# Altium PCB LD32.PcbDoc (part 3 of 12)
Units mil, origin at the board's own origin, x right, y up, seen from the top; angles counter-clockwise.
Board outline 7007.87 x 4368.85 mil, 12 copper layers (Top Layer, Int1 (GND), Int2 (AVDD), Int3 (DVDD), Int4 (GND), Int5 (ST), Int6 (SB), Int8 (AGND), Int7 (AVCC), Int9 (VCCA), Int10 (GND), Bottom Layer), stack 60.136 mil thick; 1165 components, 667 nets, 3910 pads, 2570 vias.
Unrouted connection lines stored in the file: 14.
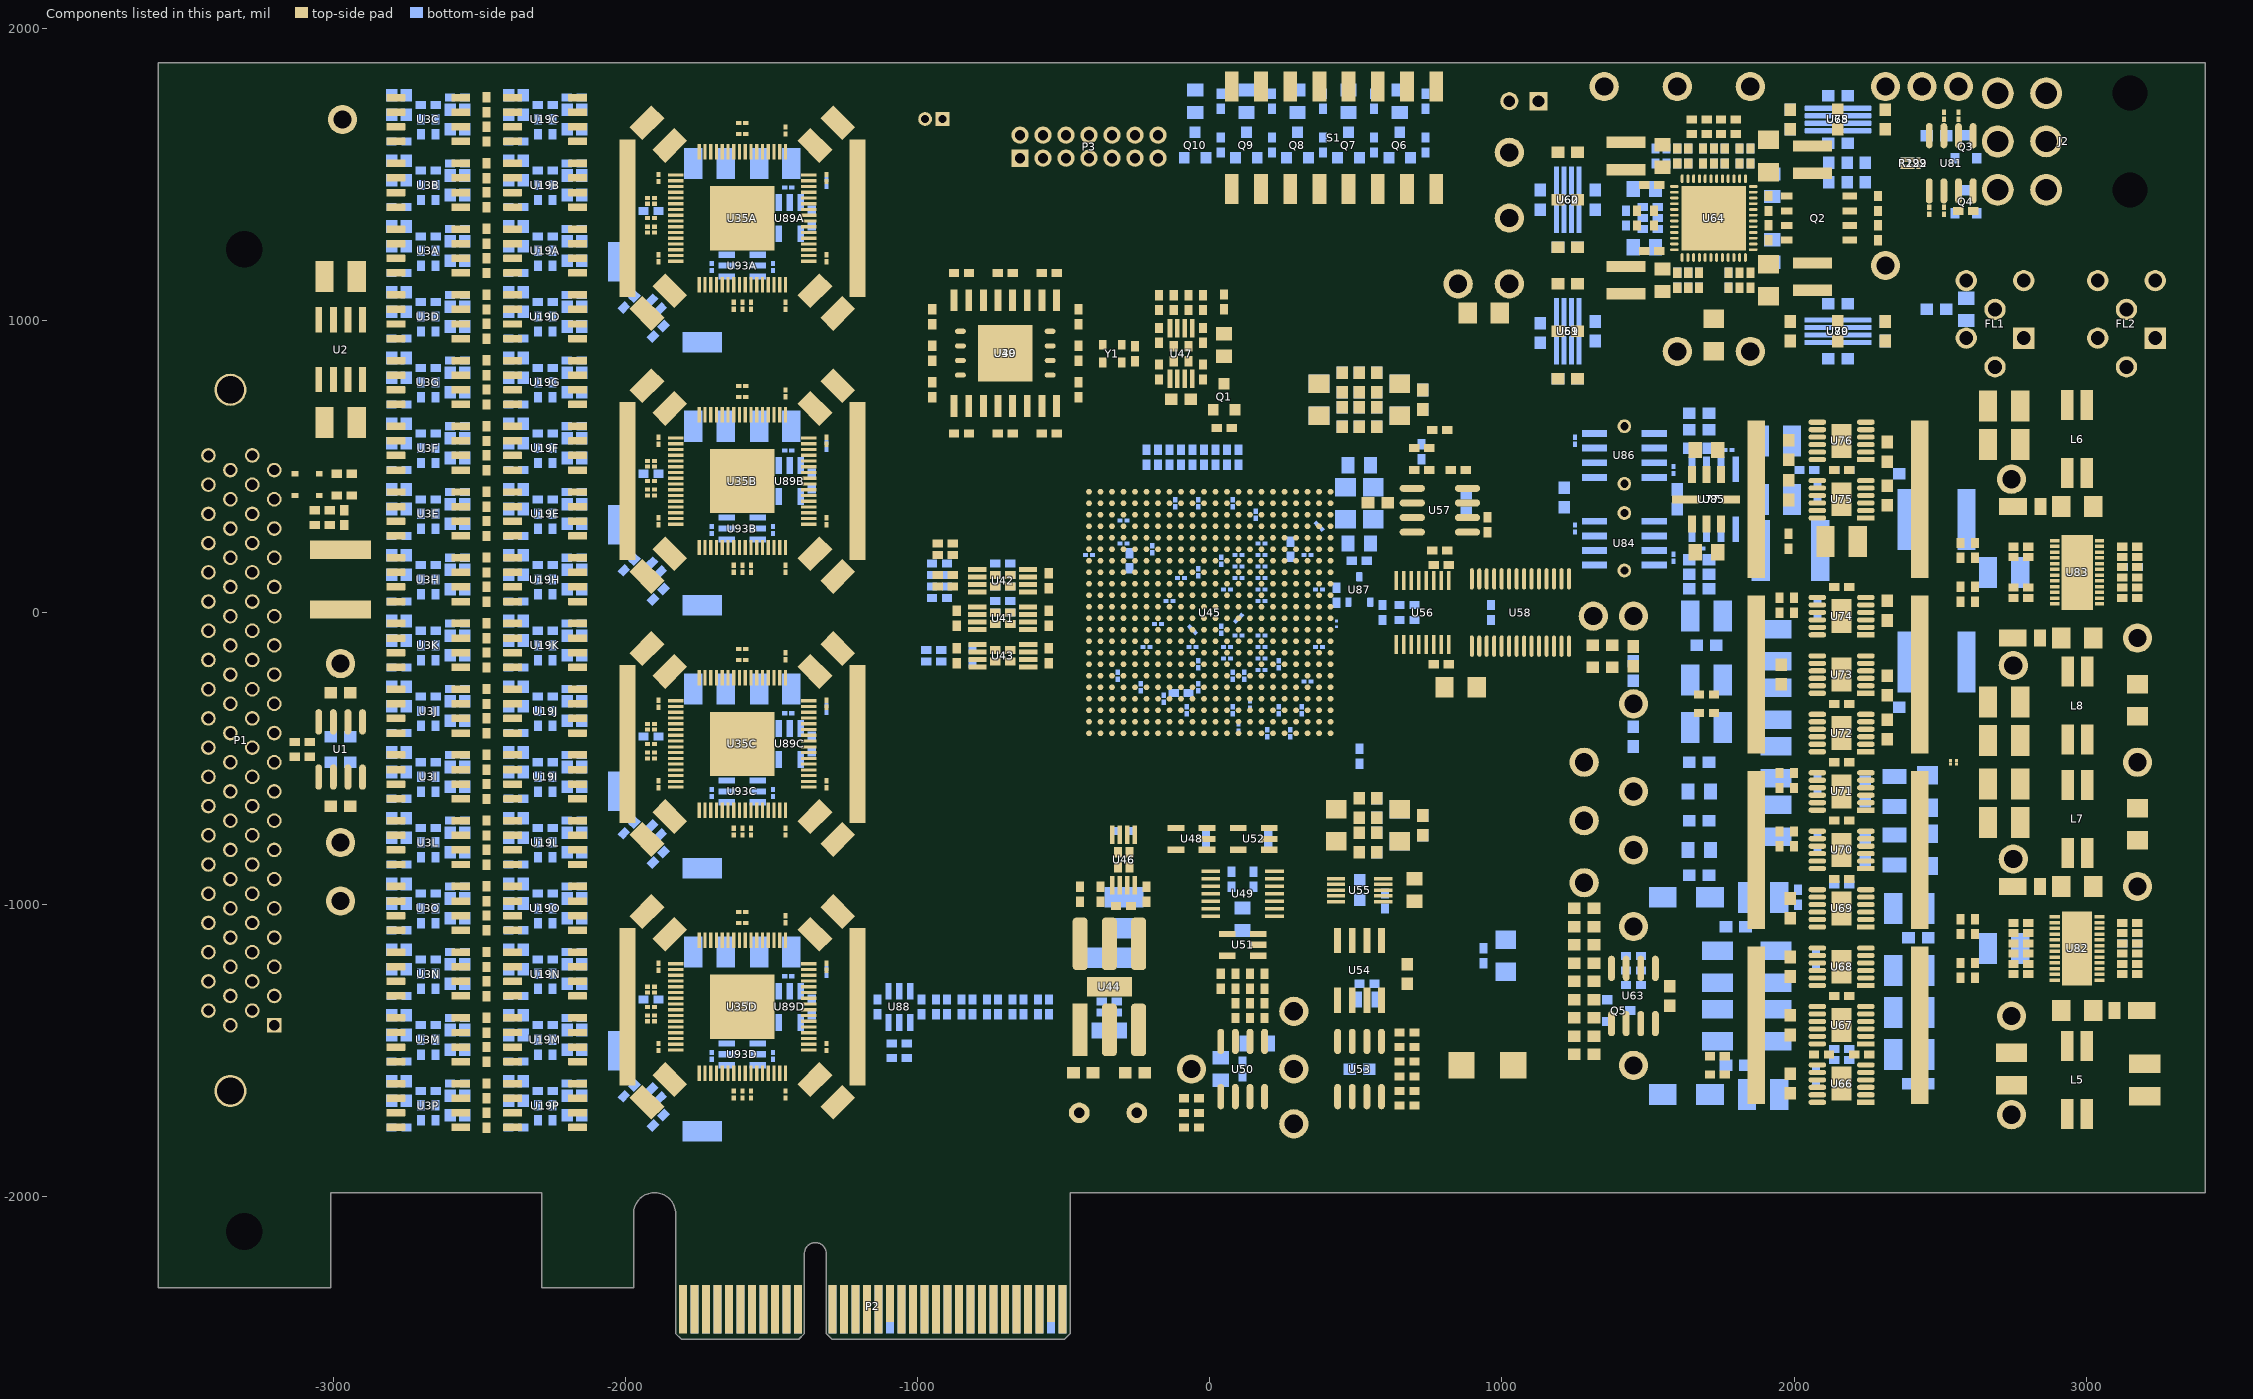
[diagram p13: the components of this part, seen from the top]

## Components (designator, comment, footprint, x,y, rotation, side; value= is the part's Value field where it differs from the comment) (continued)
U19F "OPA1612AID" D0008A_M -2275,562.5 r0 top locked (schematic designator U19)
U19G "OPA1612AID" D0008A_M -2275,787.5 r0 top locked (schematic designator U19)
U19H "OPA1612AID" D0008A_M -2275,112.5 r0 top locked (schematic designator U19)
U19I "OPA1612AID" D0008A_M -2275,-562.5 r0 top locked (schematic designator U19)
U19J "OPA1612AID" D0008A_M -2275,-337.5 r0 top locked (schematic designator U19)
U19K "OPA1612AID" D0008A_M -2275,-112.5 r0 top locked (schematic designator U19)
U19L "OPA1612AID" D0008A_M -2275,-787.5 r0 top locked (schematic designator U19)
U19M "OPA1612AID" D0008A_M -2275,-1462.5 r0 top locked (schematic designator U19)
U19N "OPA1612AID" D0008A_M -2275,-1237.5 r0 top locked (schematic designator U19)
U19O "OPA1612AID" D0008A_M -2275,-1012.5 r0 top locked (schematic designator U19)
U19P "OPA1612AID" D0008A_M -2275,-1687.5 r0 top locked (schematic designator U19)
U35A "ESS9038PRO" CP-64_3_MXM -1600,1350 r270 top locked (schematic designator U35)
U35B "ESS9038PRO" CP-64_3_MXM -1600,450 r270 top locked (schematic designator U35)
U35C "ESS9038PRO" CP-64_3_MXM -1600,-450 r270 top locked (schematic designator U35)
U35D "ESS9038PRO" CP-64_3_MXM -1600,-1350 r270 top locked (schematic designator U35)
U39 "MT25QU512ABB8ESF-0SIT" FP-002-15547-MFG -700,887.5 r90 top
U40 "S25FL256LAGNFV010" FP-002-18827-MFG -700,887.5 r180 top value=NL
U41 "SN65LVDS100D" MSOP8 -708.66,-19.68 r270 top
U42 "SN65LVDS100D" MSOP8 -708.66,108.27 r270 top
U43 "SN65LVDS100D" MSOP8 -708.66,-147.64 r90 top
U44 "67.108864MHz" BomarSiTime -343.75,-1281 r90 top
U45 "XC7A200T-2FBG484I" FBG484 0,0 r180 top locked
U46 "SN65LVDS100D" MSOP8 -295.28,-846.46 r0 top
U47 "SN65LVDS100D" MSOP8 -98.43,885.83 r180 top
U48 "SN65LVDT2" SO-G5/E2.4 -62.5,-775 r90 top
U49 "SN74LVC74APWR" TSSOP14 112.5,-962.5 r90 top
U50 "OP284FS" SO-8_N 112.5,-1562.5 r270 top
U51 "SN74LVC1G00" SO-G5/E2.4 112.5,-1137.5 r90 top
U52 "SN65LVDT2" SO-G5/E2.4 150,-775 r90 top
U53 "OP284FS" SO-8_N 512.5,-1562.5 r90 top
U54 "ADR4530" SO-G8 512.5,-1225 r0 top
U55 "AD7685" TSSO3x5-G10 512.5,-950 r90 top
U56 "SN74LVC4T245" TSSOP16 728.35,0 r180 top locked
U57 "OP284FS" SO-8_N 787.5,350 r180 top
U58 "ADG706BRU" ADI-RU-28_M 1062.99,0 r270 top
U59 "INA333AIDGKR" DGK0008A_N 1225,962.5 r270 bottom
U60 "INA333AIDGKR" DGK0008A_N 1225,1412.5 r270 bottom
U61 "INA350" FP-RJ-8-IPC_B 1225,962.5 r270 bottom value=NL
U62 "INA350" FP-RJ-8-IPC_B 1225,1412.5 r270 bottom value=NL
U63 "OP284FS" SO-8_N 1450,-1312.5 r90 top
U64 "ADP5052ACPZ-R7" CP-48-13_L 1725,1350 r0 top
U65 "INA333AIDGKR" DGK0008A_N 2150,1687.5 r180 bottom
U66 "LT3094IMSE#PBF" FP-MSE-12-05-08-1666-IPC_B 2162.5,-1612.5 r180 top locked
U67 "LT3094IMSE#PBF" FP-MSE-12-05-08-1666-IPC_B 2162.5,-1412.5 r180 top locked
U68 "LT3045EMSE#TRPBF" FP-MSE-12-05-08-1666-IPC_B 2162.5,-1212.5 r180 top locked
U69 "LT3045EMSE#TRPBF" FP-MSE-12-05-08-1666-IPC_B 2162.5,-1012.5 r180 top locked
U70 "LT3045EMSE#TRPBF" FP-MSE-12-05-08-1666-IPC_B 2162.5,-812.5 r180 top locked
U71 "LT3045EMSE#TRPBF" FP-MSE-12-05-08-1666-IPC_B 2162.5,-612.5 r180 top locked
U72 "LT3045EMSE#TRPBF" FP-MSE-12-05-08-1666-IPC_B 2162.5,-412.5 r180 top locked
U73 "LT3045EMSE#TRPBF" FP-MSE-12-05-08-1666-IPC_B 2162.5,-212.5 r180 top locked
U74 "LT3045EMSE#TRPBF" FP-MSE-12-05-08-1666-IPC_B 2162.5,-12.5 r180 top locked
U75 "LT3045EMSE#TRPBF" FP-MSE-12-05-08-1666-IPC_B 2162.5,387.5 r180 top locked
U76 "LT3045EMSE#TRPBF" FP-MSE-12-05-08-1666-IPC_B 2162.5,587.5 r180 top locked
U77 "LTC6655BHLS8-4.096#PBF" FP-LS8-8-05-08-1852-MFG 1700,387.5 r90 top
U78 "INA350" FP-RJ-8-IPC_B 2150,1687.5 r180 bottom value=NL
U79 "INA333AIDGKR" DGK0008A_N 2150,962.5 r0 bottom
U80 "INA350" FP-RJ-8-IPC_B 2150,962.5 r0 bottom value=NL
U81 "OP284FS" SO-8_N 2537.5,1537.5 r270 top
U82 "LT8582EDKD" DFN-24_DKD#1 2968.75,-1150 r0 top
U83 "LT8582EDKD" DFN-24_DKD#2 2968.75,137.5 r0 top
U84 "ADA4625" SO-G8 1418.75,237.5 r90 bottom
U85 "ADA4625" SO-G8 1725,387.5 r180 bottom
U86 "ADA4625" SO-G8 1418.75,537.5 r270 bottom
U87 "REF3012AIDBZT" DBZ0003A_L 511.81,78.74 r90 bottom
U88 "SN74AVC1T45" SO-G6/E2.4 -1062.5,-1350 r0 bottom
U89A "SN65LVDT2" SO-G5/E2.4 -1437.5,1350 r0 bottom locked (schematic designator U89)
U89B "SN65LVDT2" SO-G5/E2.4 -1437.5,450 r0 bottom locked (schematic designator U89)
U89C "SN65LVDT2" SO-G5/E2.4 -1437.5,-450 r0 bottom locked (schematic designator U89)
U89D "SN65LVDT2" SO-G5/E2.4 -1437.5,-1350 r0 bottom locked (schematic designator U89)
U93A "SN74AVC1T45" SO-G6/E2.4 -1600,1187.5 r90 bottom locked (schematic designator U93)
U93B "SN74AVC1T45" SO-G6/E2.4 -1600,287.5 r90 bottom locked (schematic designator U93)
U93C "SN74AVC1T45" SO-G6/E2.4 -1600,-612.5 r90 bottom locked (schematic designator U93)
U93D "SN74AVC1T45" SO-G6/E2.4 -1600,-1512.5 r90 bottom locked (schematic designator U93)
W1 "Net tie" NETTIE1_SMDTOP 2555,-518.75 r180 top net-tie
W2 "Net tie" NETTIE1_SMDTOP 2555,-506.25 r180 top net-tie
W3 "NL" NETTIE1_SMDTOP 433.07,-48.87 r90 bottom net-tie
Y1 "DSC1001DI1-100.0000T" FP-CDFN2520-4LD-PL-1-MFG -334.65,885.83 r270 top

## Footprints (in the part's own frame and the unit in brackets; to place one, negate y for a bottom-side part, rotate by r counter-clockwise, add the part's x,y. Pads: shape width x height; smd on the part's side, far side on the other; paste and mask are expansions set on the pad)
2MM_HDR2X7_RA [mm] "Connector; 2mm Header; 7x2 Position, RA"
  rect 1.5x1.5 hole 0.9: 1(0,0)
  round 1.5 hole 0.9: 2(0,2) 3(2,0) 4(2,2) 5(4,0) 6(4,2) 7(6,0) 8(6,2) 9(8,0) 10(8,2) 11(10,0) 12(10,2) 13(12,0) 14(12,2)
  silkscreen extent -2.29,-1.27 14.22,8.38, body extent -2.32,-0.27 14.33,8.38, height 6.3
455580003 [mm]
  round 2.775 hole 1.85: 1(0,0) 2(4.191,0) 3(8.4,0) 4(0,-4.2) 5(4.2,-4.2) 6(8.4,-4.2)
  round 1.525 hole 3.05 unplated: MH1(0,7.3) MH2(8.4,7.3)
  silkscreen extent -2.7,1.1 11.1,13.9, body extent -3.14,-4.78 11.06,13.86, height 11.53
ADI-RU-28_M [mm] "SOP, 28-Leads, Body 9.7x4.4mm, Pitch 0.65mm, IPC Low Density"
  oval 1.85x0.35 smd: 1(-2.925,4.225) 2(-2.925,3.575) 3(-2.925,2.925) 4(-2.925,2.275) 5(-2.925,1.625) 6(-2.925,0.975) 7(-2.925,0.325) 8(-2.925,-0.325) 9(-2.925,-0.975) 10(-2.925,-1.625) 11(-2.925,-2.275) 12(-2.925,-2.925) 13(-2.925,-3.575) 14(-2.925,-4.225) 15(2.925,-4.225) 16(2.925,-3.575) 17(2.925,-2.925) 18(2.925,-2.275) 19(2.925,-1.625) 20(2.925,-0.975) 21(2.925,-0.325) 22(2.925,0.325) 23(2.925,0.975) 24(2.925,1.625) 25(2.925,2.275) 26(2.925,2.925) 27(2.925,3.575) 28(2.925,4.225)
  silkscreen extent -3.05,-4.9 1.6,5.08, body extent -2.25,-4.9 2.25,4.9, height 1.2
BomarSiTime [mm] "VCXO 14.3 x 8.7 mm or 7.0 x 5.0 mm"
  rect 4.572x1.3 smd: 1(-3.74,2.54)
  rrect50% 4.572x1.3 smd: 2(-3.74,0) 3(-3.74,-2.54) 4(3.727,-2.54) 5(3.727,0) 6(3.727,2.54)
  rect 1.7x3.9 smd: 7(-0.007,0)
  silkscreen extent -6.81,-7.21 4.9,7.29, body extent -4.76,-7.11 4.79,7.19, height 5.9
CC0603-0201 [mil] "Chip Capacitor; Body 0.6 x 0.3 mm (LxW typ)"
  rect 17.97x14.28 smd mask+2: 1(-11.94,0) 2(11.94,0)
  body extent -12,-6 12,6, height 13
CC1005-0402 [mm] "Chip Capacitor; Body 1.0 x 0.5 mm (LxW typ)"
  rect 0.9x0.7 smd: 1(-0.65,0) 2(0.65,0)
  body extent -0.53,-0.28 0.52,0.27, height 0.55
CC1608-0603 [mm] "Chip Capacitor; Body 1.6 x 0.8 mm (LxW typ)"
  rect 1.1x1 smd: 1(-0.85,0) 2(0.85,0)
  silkscreen extent -1.7,-0.4 -1.7,0.4, body extent -0.88,-0.48 0.87,0.47, height 0.87
CC2013-0805 [mm] "Chip Capacitor; Body 2.0 x 1.3 mm (LxW typ)"
  rect 1.15x1.4 smd: 1(-0.975,0) 2(0.975,0)
  silkscreen extent -1.85,-0.6 -1.85,0.6, body extent -1.1,-0.72 1.1,0.73, height 0.88
CC3216-1206 [mm] "Chip Capacitor; Body 3.2 x 1.6 mm (LxW typ)"
  rect 1.6x1.8 smd: 1(-1.4,0) 2(1.4,0)
  silkscreen extent -0.3,-0.8 0.3,0.8, body extent -1.85,-0.97 1.85,0.97, height 0.88
CC3225-1210 [mm] "Chip Capacitor; Body 3.2 x 2.5 mm (LxW typ)"
  rect 1.6x2.7 smd: 1(-1.4,0) 2(1.4,0)
  silkscreen extent -0.3,-1.25 0.3,1.25, body extent -1.85,-1.45 1.85,1.45, height 1.4
CC5650-2220 [mm] "Chip Capacitor, Body 5.6 x 5.0mm (LxW typ)"
  rect 1.6x5.3 smd: 1(-2.6,0) 2(2.6,0)
  silkscreen extent -1.4,-2.55 1.4,2.55, body extent -3.05,-2.7 3.05,2.7, height 1.8
CL2520-1008 [mm] "Chip Inductor; Body 2.54 x 2.0 mm (LxW typ)"
  rect 1.3x2.1 smd: 1(-1.3,0) 2(1.3,0)
  silkscreen extent -2.25,-1 -2.25,1, body extent -1.46,-1.39 1.46,1.4, height 2.02
CP-48-13_L [mm] "QFN, 48-Leads, Body 7x7mm, Pitch 0.5mm, Thermal Pad 5.6x5.6mm, IPC High Density"
  oval 0.75x0.25 smd: 1(-3.425,2.75) 2(-3.425,2.25) 3(-3.425,1.75) 4(-3.425,1.25) 5(-3.425,0.75) 6(-3.425,0.25) 7(-3.425,-0.25) 8(-3.425,-0.75) 9(-3.425,-1.25) 10(-3.425,-1.75) 11(-3.425,-2.25) 12(-3.425,-2.75) 25(3.425,-2.75) 26(3.425,-2.25) 27(3.425,-1.75) 28(3.425,-1.25) 29(3.425,-0.75) 30(3.425,-0.25) 31(3.425,0.25) 32(3.425,0.75) 33(3.425,1.25) 34(3.425,1.75) 35(3.425,2.25) 36(3.425,2.75)
  oval 0.25x0.75 smd: 13(-2.75,-3.425) 14(-2.25,-3.425) 15(-1.75,-3.425) 16(-1.25,-3.425) 17(-0.75,-3.425) 18(-0.25,-3.425) 19(0.25,-3.425) 20(0.75,-3.425) 21(1.25,-3.425) 22(1.75,-3.425) 23(2.25,-3.425) 24(2.75,-3.425) 37(2.75,3.425) 38(2.25,3.425) 39(1.75,3.425) 40(1.25,3.425) 41(0.75,3.425) 42(0.25,3.425) 43(-0.25,3.425) 44(-0.75,3.425) 45(-1.25,3.425) 46(-1.75,3.425) 47(-2.25,3.425) 48(-2.75,3.425)
  rect 5.6x5.6 smd paste-2.7: 49(0,0)
  silkscreen extent -4.47,-3.7 3.7,3.7
CP-64_3_MXM [mil] "QFN, 64-Leads, Body 10x10mm, Pitch 0.5mm, Thermal Pad 5.3x5.3mm"
  rect 53x11 smd: 1(-227.5,147.64) 2(-227.5,127.95) 3(-227.5,108.27) 4(-227.5,88.58) 5(-227.5,68.9) 6(-227.5,49.21) 7(-227.5,29.53) 8(-227.5,9.84) 9(-227.5,-9.84) 10(-227.5,-29.53) 11(-227.5,-49.21) 12(-227.5,-68.9) 13(-227.5,-88.58) 14(-227.5,-108.27) 15(-227.5,-127.95) 16(-227.5,-147.64) 33(227.5,-147.64) 34(227.5,-127.95) 35(227.5,-108.27) 36(227.5,-88.58) 37(227.5,-68.9) 38(227.5,-49.21) 39(227.5,-29.53) 40(227.5,-9.84) 41(227.5,9.84) 42(227.5,29.53) 43(227.5,49.21) 44(227.5,68.9) 45(227.5,88.58) 46(227.5,108.27) 47(227.5,127.95) 48(227.5,147.64)
  rect 11x53 smd: 17(-147.64,-227.5) 18(-127.95,-227.5) 19(-108.27,-227.5) 20(-88.58,-227.5) 21(-68.9,-227.5) 22(-49.21,-227.5) 23(-29.53,-227.5) 24(-9.84,-227.5) 25(9.84,-227.5) 26(29.53,-227.5) 27(49.21,-227.5) 28(68.9,-227.5) 29(88.58,-227.5) 30(108.27,-227.5) 31(127.95,-227.5) 32(147.64,-227.5) 49(147.64,227.5) 50(127.95,227.5) 51(108.27,227.5) 52(88.58,227.5) 53(68.9,227.5) 54(49.21,227.5) 55(29.53,227.5) 56(9.84,227.5) 57(-9.84,227.5) 58(-29.53,227.5) 59(-49.21,227.5) 60(-68.9,227.5) 61(-88.58,227.5) 62(-108.27,227.5) 63(-127.95,227.5) 64(-147.64,227.5)
  rect 220.47x220.47 smd paste-1181.1: 65(0,0)
  silkscreen extent -274,-274 274,274, body extent -240,-240 240,240, height 47
CR0603-0201 [mil] "Chip Resistor; Body 0.6 x 0.3 mm (LxW typ)"
  rect 17.97x14.28 smd mask+2: 1(-11.94,0) 2(11.94,0)
  body extent -12,-6 12,6, height 10
CR0816-0306-4P [mm] "4-terminal current sensor"
  rect 0.4x1.2 smd: 1(-0.3,-0.275) 4(0.3,-0.275)
  rect 0.4x0.35 smd: 2(-0.3,0.7) 3(0.3,0.7)
  silkscreen extent -0.77,0.65 -0.67,0.75, body extent -0.39,-0.8 0.39,0.8, height 0.5
CR1005-0402 [mm] "Chip Resistor; Body 1.1 x 0.5 mm (LxW typ)"
  rect 0.9x0.7 smd: 1(-0.65,0) 2(0.65,0)
  body extent -0.5,-0.25 0.5,0.25, height 0.32
CR1608-0603 [mm] "Chip Resistor; Body 1.6 x 0.8 mm (LxW typ)"
  rect 1.1x1 smd: 1(-0.85,0) 2(0.85,0)
  body extent -0.76,-0.43 0.79,0.42, height 0.46
D0008A_M [mm] "SOIC, 8-Leads, Body 5x4mm, Pitch 1.27mm, IPC Low Density"
  rrect15% 1.65x0.65 smd: 1(-2.825,1.905) 2(-2.825,0.635) 3(-2.825,-0.635) 4(-2.825,-1.905) 5(2.825,-1.905) 6(2.825,-0.635) 7(2.825,0.635) 8(2.825,1.905)
  silkscreen extent -2.95,-2.5 1.6,2.9, body extent -3,-2.45 3,2.45, height 1.63
DBZ0003A_L [mm] "SOT23, 3-Leads, Body 3.04x1.4mm, Pitch 0.95mm, IPC High Density"
  rrect18% 0.8x0.55 smd: 1(-1.1,0.95) 2(-1.1,-0.95) 3(1.1,0)
  silkscreen extent -1.22,-1.5 0.7,1.9, body extent -1.26,-1.46 1.26,1.46, height 0.96
DFN-24_DKD#1 [mil] "24-Lead Plastic DFN (7mm × 3mm)"
  rect 35x12 smd: 1(-76.5,108.27) 2(-76.5,88.58) 3(-76.5,68.9) 4(-76.5,49.21) 5(-76.5,29.53) 6(-76.5,9.84) 7(-76.5,-9.84) 8(-76.5,-29.53) 9(-76.5,-49.21) 10(-76.5,-68.9) 11(-76.5,-88.58) 12(-76.5,-108.27) 13(76.5,-108.27) 14(76.5,-88.58) 15(76.5,-68.9) 16(76.5,-49.21) 17(76.5,-29.53) 18(76.5,-9.84) 19(76.5,9.84) 20(76.5,29.53) 21(76.5,49.21) 22(76.5,68.9) 23(76.5,88.58) 24(76.5,108.27)
  rect 102.87x252.09 smd paste+0 mask+0: 25(0,0)
  silkscreen extent -109,-145 86,145, body extent -81,-140 81,140, height 32
DFN-24_DKD#2 [mil] "24-Lead Plastic DFN (7mm × 3mm)"
  rect 32x12 smd: 1(-76.5,108.27) 2(-76.5,88.58) 3(-76.5,68.9) 4(-76.5,49.21) 5(-76.5,29.53) 6(-76.5,9.84) 7(-76.5,-9.84) 8(-76.5,-29.53) 9(-76.5,-49.21) 10(-76.5,-68.9) 11(-76.5,-88.58) 12(-76.5,-108.27) 13(76.5,-108.27) 14(76.5,-88.58) 15(76.5,-68.9) 16(76.5,-49.21) 17(76.5,-29.53) 18(76.5,-9.84) 19(76.5,9.84) 20(76.5,29.53) 21(76.5,49.21) 22(76.5,68.9) 23(76.5,88.58) 24(76.5,108.27)
  rect 107.87x257.09 smd paste+0 mask+0: 25(0,0)
  silkscreen extent -109,-145 86,145, body extent -81,-140 81,140, height 32
DGK0008A_N [mm] "TSOP, 8-Leads, Body 3.1x3.1mm, Pitch 0.65mm, IPC Medium Density"
  rrect22% 1.35x0.45 smd: 1(-2.225,0.975) 2(-2.225,0.325) 3(-2.225,-0.325) 4(-2.225,-0.975) 5(2.225,-0.975) 6(2.225,-0.325) 7(2.225,0.325) 8(2.225,0.975)
  silkscreen extent -2.35,-1.55 1.15,1.9, body extent -2.45,-1.5 2.45,1.5, height 0.94
DIP_SW_8WAY_SMD_SIDE [mm] "DIP Switch; 16 Leads, right-angle"
  rect 1.2x2.6 smd: 1(-8.89,-4.45) 2(-6.35,-4.45) 3(-3.81,-4.45) 4(-1.27,-4.45) 5(1.27,-4.45) 6(3.81,-4.45) 7(6.35,-4.45) 8(8.89,-4.45) 9(8.89,4.45) 10(6.35,4.45) 11(3.81,4.45) 12(1.27,4.45) 13(-1.27,4.45) 14(-3.81,4.45) 15(-6.35,4.45) 16(-8.89,4.45)
  silkscreen extent -10.29,-2.5 10.31,2.5, body extent -11.15,-6.5 11.15,4.65, height 6.98
DO-PowerDI123 [mm] "POWERDI123, Body 3.7 x 1.8 mm, inc. leads (LxW)"
  rect 1.05x1.5 smd: 1(-1.525,0)
  rect 2.4x1.5 smd: 2(0.85,0)
  silkscreen extent -2.29,-1.02 2.29,1.02, body extent -1.85,-0.89 1.85,0.89, height 0.98
DO-SMA [mm] "DO-214-AC/SMA; 2 C-Bend Leads; Body 5 x 2.7 mm, inc. leads (LxW)"
  rect 2.4x1.8 smd: 1(-2.05,0) 2(2.05,0)
  silkscreen extent -3.65,-1.3 3.95,1.3, body extent -2.74,-1.4 2.74,1.4, height 2.41
DO-SMB [mm] "DO-214-AA/SMB; 2 C-Bend Leads; Body 5.3 x 3.6 mm, inc. leads (LxW)"
  rect 2.3x2.3 smd: 1(-2.25,0) 2(2.25,0)
  silkscreen extent -3.8,-1.55 4.1,1.55, body extent -2.75,-1.95 2.75,1.95, height 2.45
ECQPZ120060-5.0 [mm] "Polypropylene Film Capacitor; Body 12.0 x 6.0 mm (LxW typ); 5.0mm lead spacing"
  round 1.8 hole 0.9: 1(0,0) 2(5,0)
  silkscreen extent -3.5,-3 8.5,3
FBG484 [mm] "BGA, 484-Balls, Body 23x23mm, Pitch 1.0mm"
  round 0.5 smd: A1(-10.5,10.5) A2(-9.5,10.5) A3(-8.5,10.5) A4(-7.5,10.5) A5(-6.5,10.5) A6(-5.5,10.5) A7(-4.5,10.5) A8(-3.5,10.5) A9(-2.5,10.5) A10(-1.5,10.5) A11(-0.5,10.5) A12(0.5,10.5) A13(1.5,10.5) A14(2.5,10.5) A15(3.5,10.5) A16(4.5,10.5) A17(5.5,10.5) A18(6.5,10.5) A19(7.5,10.5) A20(8.5,10.5) A21(9.5,10.5) A22(10.5,10.5) AA1(-10.5,-9.5) AA2(-9.5,-9.5) AA3(-8.5,-9.5) AA4(-7.5,-9.5) AA5(-6.5,-9.5) AA6(-5.5,-9.5) AA7(-4.5,-9.5) AA8(-3.5,-9.5) AA9(-2.5,-9.5) AA10(-1.5,-9.5) AA11(-0.5,-9.5) AA12(0.5,-9.5) AA13(1.5,-9.5) AA14(2.5,-9.5) AA15(3.5,-9.5) AA16(4.5,-9.5) AA17(5.5,-9.5) AA18(6.5,-9.5) AA19(7.5,-9.5) AA20(8.5,-9.5) AA21(9.5,-9.5) AA22(10.5,-9.5) AB1(-10.5,-10.5) AB2(-9.5,-10.5) AB3(-8.5,-10.5) AB4(-7.5,-10.5) AB5(-6.5,-10.5) AB6(-5.5,-10.5) AB7(-4.5,-10.5) AB8(-3.5,-10.5) AB9(-2.5,-10.5) AB10(-1.5,-10.5) AB11(-0.5,-10.5) AB12(0.5,-10.5) AB13(1.5,-10.5) AB14(2.5,-10.5) AB15(3.5,-10.5) AB16(4.5,-10.5) AB17(5.5,-10.5) AB18(6.5,-10.5) AB19(7.5,-10.5) AB20(8.5,-10.5) AB21(9.5,-10.5) AB22(10.5,-10.5) B1(-10.5,9.5) B2(-9.5,9.5) B3(-8.5,9.5) B4(-7.5,9.5) B5(-6.5,9.5) B6(-5.5,9.5) B7(-4.5,9.5) B8(-3.5,9.5) B9(-2.5,9.5) B10(-1.5,9.5) B11(-0.5,9.5) B12(0.5,9.5) B13(1.5,9.5) B14(2.5,9.5) B15(3.5,9.5) B16(4.5,9.5) B17(5.5,9.5) B18(6.5,9.5) B19(7.5,9.5) B20(8.5,9.5) B21(9.5,9.5) B22(10.5,9.5) C1(-10.5,8.5) C2(-9.5,8.5) C3(-8.5,8.5) C4(-7.5,8.5) C5(-6.5,8.5) C6(-5.5,8.5) C7(-4.5,8.5) C8(-3.5,8.5) C9(-2.5,8.5) C10(-1.5,8.5) C11(-0.5,8.5) C12(0.5,8.5) C13(1.5,8.5) C14(2.5,8.5) C15(3.5,8.5) C16(4.5,8.5) C17(5.5,8.5) C18(6.5,8.5) C19(7.5,8.5) C20(8.5,8.5) C21(9.5,8.5) C22(10.5,8.5) D1(-10.5,7.5) D2(-9.5,7.5) D3(-8.5,7.5) D4(-7.5,7.5) D5(-6.5,7.5) D6(-5.5,7.5) D7(-4.5,7.5) D8(-3.5,7.5) D9(-2.5,7.5) D10(-1.5,7.5) D11(-0.5,7.5) D12(0.5,7.5) D13(1.5,7.5) D14(2.5,7.5) D15(3.5,7.5) D16(4.5,7.5) D17(5.5,7.5) D18(6.5,7.5) D19(7.5,7.5) D20(8.5,7.5) D21(9.5,7.5) D22(10.5,7.5) E1(-10.5,6.5) E2(-9.5,6.5) E3(-8.5,6.5) E4(-7.5,6.5) E5(-6.5,6.5) E6(-5.5,6.5) E7(-4.5,6.5) E8(-3.5,6.5) E9(-2.5,6.5) E10(-1.5,6.5) E11(-0.5,6.5) E12(0.5,6.5) E13(1.5,6.5) E14(2.5,6.5) E15(3.5,6.5) E16(4.5,6.5) E17(5.5,6.5) E18(6.5,6.5) E19(7.5,6.5) E20(8.5,6.5) E21(9.5,6.5) E22(10.5,6.5) F1(-10.5,5.5) F2(-9.5,5.5) F3(-8.5,5.5) F4(-7.5,5.5) F5(-6.5,5.5) F6(-5.5,5.5) F7(-4.5,5.5) F8(-3.5,5.5) F9(-2.5,5.5) F10(-1.5,5.5) F11(-0.5,5.5) F12(0.5,5.5) F13(1.5,5.5) F14(2.5,5.5) F15(3.5,5.5) F16(4.5,5.5) F17(5.5,5.5) F18(6.5,5.5) F19(7.5,5.5) F20(8.5,5.5) F21(9.5,5.5) F22(10.5,5.5) G1(-10.5,4.5) G2(-9.5,4.5) G3(-8.5,4.5) G4(-7.5,4.5) G5(-6.5,4.5) G6(-5.5,4.5) G7(-4.5,4.5) G8(-3.5,4.5) G9(-2.5,4.5) G10(-1.5,4.5) G11(-0.5,4.5) G12(0.5,4.5) G13(1.5,4.5) G14(2.5,4.5) G15(3.5,4.5) G16(4.5,4.5) G17(5.5,4.5) G18(6.5,4.5) G19(7.5,4.5) G20(8.5,4.5) G21(9.5,4.5) G22(10.5,4.5) H1(-10.5,3.5) H2(-9.5,3.5) H3(-8.5,3.5) H4(-7.5,3.5) H5(-6.5,3.5) H6(-5.5,3.5) H7(-4.5,3.5) H8(-3.5,3.5) H9(-2.5,3.5) H10(-1.5,3.5) H11(-0.5,3.5) H12(0.5,3.5) H13(1.5,3.5) H14(2.5,3.5) H15(3.5,3.5) H16(4.5,3.5) H17(5.5,3.5) H18(6.5,3.5) H19(7.5,3.5) H20(8.5,3.5) H21(9.5,3.5) H22(10.5,3.5) J1(-10.5,2.5) J2(-9.5,2.5) J3(-8.5,2.5) J4(-7.5,2.5) J5(-6.5,2.5) J6(-5.5,2.5) J7(-4.5,2.5) J8(-3.5,2.5) J9(-2.5,2.5) J10(-1.5,2.5) J11(-0.5,2.5) J12(0.5,2.5) J13(1.5,2.5) J14(2.5,2.5) J15(3.5,2.5) J16(4.5,2.5) J17(5.5,2.5) J18(6.5,2.5) J19(7.5,2.5) J20(8.5,2.5) J21(9.5,2.5) J22(10.5,2.5) K1(-10.5,1.5) K2(-9.5,1.5) K3(-8.5,1.5) K4(-7.5,1.5) K5(-6.5,1.5) K6(-5.5,1.5) K7(-4.5,1.5) K8(-3.5,1.5) K9(-2.5,1.5) K10(-1.5,1.5) K11(-0.5,1.5) K12(0.5,1.5) K13(1.5,1.5) K14(2.5,1.5) K15(3.5,1.5) K16(4.5,1.5) K17(5.5,1.5) K18(6.5,1.5) K19(7.5,1.5) K20(8.5,1.5) K21(9.5,1.5) K22(10.5,1.5) L1(-10.5,0.5) L2(-9.5,0.5) L3(-8.5,0.5) L4(-7.5,0.5) L5(-6.5,0.5) L6(-5.5,0.5) L7(-4.5,0.5) L8(-3.5,0.5) L9(-2.5,0.5) L10(-1.5,0.5) L11(-0.5,0.5) L12(0.5,0.5) L13(1.5,0.5) L14(2.5,0.5) L15(3.5,0.5) L16(4.5,0.5) L17(5.5,0.5) L18(6.5,0.5) L19(7.5,0.5) L20(8.5,0.5) L21(9.5,0.5) L22(10.5,0.5) M1(-10.5,-0.5) M2(-9.5,-0.5) M3(-8.5,-0.5) M4(-7.5,-0.5) M5(-6.5,-0.5) M6(-5.5,-0.5) M7(-4.5,-0.5) M8(-3.5,-0.5) M9(-2.5,-0.5) M10(-1.5,-0.5) M11(-0.5,-0.5) M12(0.5,-0.5) M13(1.5,-0.5) M14(2.5,-0.5) M15(3.5,-0.5) M16(4.5,-0.5) M17(5.5,-0.5) M18(6.5,-0.5) M19(7.5,-0.5) M20(8.5,-0.5) M21(9.5,-0.5) M22(10.5,-0.5) N1(-10.5,-1.5) N2(-9.5,-1.5) N3(-8.5,-1.5) N4(-7.5,-1.5) N5(-6.5,-1.5) N6(-5.5,-1.5) N7(-4.5,-1.5) N8(-3.5,-1.5) N9(-2.5,-1.5) N10(-1.5,-1.5) N11(-0.5,-1.5) N12(0.5,-1.5) N13(1.5,-1.5) N14(2.5,-1.5) N15(3.5,-1.5) N16(4.5,-1.5) N17(5.5,-1.5) N18(6.5,-1.5) N19(7.5,-1.5) N20(8.5,-1.5) N21(9.5,-1.5) N22(10.5,-1.5) P1(-10.5,-2.5) P2(-9.5,-2.5) P3(-8.5,-2.5) P4(-7.5,-2.5) P5(-6.5,-2.5) P6(-5.5,-2.5) P7(-4.5,-2.5) P8(-3.5,-2.5) P9(-2.5,-2.5) P10(-1.5,-2.5) P11(-0.5,-2.5) P12(0.5,-2.5) P13(1.5,-2.5) P14(2.5,-2.5) P15(3.5,-2.5) P16(4.5,-2.5) P17(5.5,-2.5) P18(6.5,-2.5) P19(7.5,-2.5) P20(8.5,-2.5) P21(9.5,-2.5) P22(10.5,-2.5) R1(-10.5,-3.5) R2(-9.5,-3.5) R3(-8.5,-3.5) R4(-7.5,-3.5) R5(-6.5,-3.5) R6(-5.5,-3.5) R7(-4.5,-3.5) R8(-3.5,-3.5) R9(-2.5,-3.5) R10(-1.5,-3.5) R11(-0.5,-3.5) R12(0.5,-3.5) R13(1.5,-3.5) R14(2.5,-3.5) R15(3.5,-3.5) R16(4.5,-3.5) R17(5.5,-3.5) R18(6.5,-3.5) R19(7.5,-3.5) R20(8.5,-3.5) R21(9.5,-3.5) R22(10.5,-3.5) T1(-10.5,-4.5) T2(-9.5,-4.5) T3(-8.5,-4.5) T4(-7.5,-4.5) T5(-6.5,-4.5) T6(-5.5,-4.5) T7(-4.5,-4.5) T8(-3.5,-4.5) T9(-2.5,-4.5) T10(-1.5,-4.5) T11(-0.5,-4.5) T12(0.5,-4.5) T13(1.5,-4.5) T14(2.5,-4.5) T15(3.5,-4.5) T16(4.5,-4.5) T17(5.5,-4.5) T18(6.5,-4.5) T19(7.5,-4.5) T20(8.5,-4.5) T21(9.5,-4.5) T22(10.5,-4.5) U1(-10.5,-5.5) U2(-9.5,-5.5) U3(-8.5,-5.5) U4(-7.5,-5.5) U5(-6.5,-5.5) U6(-5.5,-5.5) U7(-4.5,-5.5) U8(-3.5,-5.5) U9(-2.5,-5.5) U10(-1.5,-5.5) U11(-0.5,-5.5) U12(0.5,-5.5) U13(1.5,-5.5) U14(2.5,-5.5) U15(3.5,-5.5) U16(4.5,-5.5) U17(5.5,-5.5) U18(6.5,-5.5) U19(7.5,-5.5) U20(8.5,-5.5) U21(9.5,-5.5) U22(10.5,-5.5) V1(-10.5,-6.5) V2(-9.5,-6.5) V3(-8.5,-6.5) V4(-7.5,-6.5) V5(-6.5,-6.5) V6(-5.5,-6.5) V7(-4.5,-6.5) V8(-3.5,-6.5) V9(-2.5,-6.5) V10(-1.5,-6.5) V11(-0.5,-6.5) V12(0.5,-6.5) V13(1.5,-6.5) V14(2.5,-6.5) V15(3.5,-6.5) V16(4.5,-6.5) V17(5.5,-6.5) V18(6.5,-6.5) V19(7.5,-6.5) V20(8.5,-6.5) V21(9.5,-6.5) V22(10.5,-6.5) W1(-10.5,-7.5) W2(-9.5,-7.5) W3(-8.5,-7.5) W4(-7.5,-7.5) W5(-6.5,-7.5) W6(-5.5,-7.5) W7(-4.5,-7.5) W8(-3.5,-7.5) W9(-2.5,-7.5) W10(-1.5,-7.5) W11(-0.5,-7.5) W12(0.5,-7.5) W13(1.5,-7.5) W14(2.5,-7.5) W15(3.5,-7.5) W16(4.5,-7.5) W17(5.5,-7.5) W18(6.5,-7.5) W19(7.5,-7.5) W20(8.5,-7.5) W21(9.5,-7.5) W22(10.5,-7.5) Y1(-10.5,-8.5) Y2(-9.5,-8.5) Y3(-8.5,-8.5) Y4(-7.5,-8.5) Y5(-6.5,-8.5) Y6(-5.5,-8.5) Y7(-4.5,-8.5) Y8(-3.5,-8.5) Y9(-2.5,-8.5) Y10(-1.5,-8.5) Y11(-0.5,-8.5) Y12(0.5,-8.5) Y13(1.5,-8.5) Y14(2.5,-8.5) Y15(3.5,-8.5) Y16(4.5,-8.5) Y17(5.5,-8.5) Y18(6.5,-8.5) Y19(7.5,-8.5) Y20(8.5,-8.5) Y21(9.5,-8.5) Y22(10.5,-8.5)
  silkscreen extent -12.27,-11.5 11.5,11.5, body extent -11.5,-11.5 11.5,11.5, height 2.54
FP-002-15547-MFG [mm]
  rect 1.9x0.6 smd paste+0 mask+0: 1(-4.6,4.445) 2(-4.6,3.175) 3(-4.6,1.905) 4(-4.6,0.635) 5(-4.6,-0.635) 6(-4.6,-1.905) 7(-4.6,-3.175) 8(-4.6,-4.445) 9(4.6,-4.445) 10(4.6,-3.175) 11(4.6,-1.905) 12(4.6,-0.635) 13(4.6,0.635) 14(4.6,1.905) 15(4.6,3.175) 16(4.6,4.445)
  silkscreen extent -6.25,-5.25 2.8,5.25, body extent -5.65,-5.5 5.65,5.5, height 0.25
FP-002-18827-MFG [mm]
  rrect100% 0.95x0.45 smd paste+0 mask+0: 1(-3.9,1.905) 2(-3.9,0.635) 3(-3.9,-0.635) 4(-3.9,-1.905) 5(3.9,-1.905) 6(3.9,-0.635) 7(3.9,0.635) 8(3.9,1.905)
  rect 4.75x4.9 smd paste+0 mask+0: 9(0,0)
  silkscreen extent -5.18,-3.05 4.05,3.05, body extent -4.48,-3.15 4.48,3.15, height 0.25
FP-BNX_L12MM2_W11MM2_T8MM-MFG [mm]
  rect 1.85x1.85 hole 1.2 paste-2539.97 mask+0: 1(2.5,2.5)
  round 1.85 hole 1.2 paste-2539.97 mask+0: 2(2.5,-2.5) 3(-2.5,2.5) 4(-2.5,-2.5) 5(0,0) 6(5,0)
  silkscreen extent -6.1,-5.6 6.82,5.6, body extent -6.2,-5.7 6.2,5.7, height 0.25
FP-CDFN2520-4LD-PL-1-MFG [mm]
  rect 0.85x0.65 smd paste+0 mask+0: 1(-0.775,0.825) 2(-0.775,-0.825) 3(0.775,-0.825) 4(0.775,0.825)
  silkscreen extent -1.92,-0.13 1.02,0.95, body extent -1.3,-1.38 1.3,1.38, height 0.25
FP-CL03-IPC_B [mil]
  rect 17.88x14.28 smd paste+0 mask+0: 1(-11.98,0) 2(11.98,0)
  silkscreen extent -21,-23 21,23, body extent -12,-6 12,6, height 13
FP-DA-T263-201E-TR-MFG [mil]
  rect 60x540 smd paste+0 mask+0: 1(-280,0) 2(280,0)
  silkscreen extent -516,-256 516,256, body extent -520,-274 520,274, height 10
FP-DA-T268-301E-TR-MFG [mm]
  rect 1.4x13.7 smd paste+0 mask+0: 1(-10,0) 2(10,0)
  silkscreen extent -20.25,-6.5 20.25,6.5, body extent -20.35,-6.95 20.35,6.95, height 0.25
FP-LS8-8-05-08-1852-MFG [mm]
  rect 1.5x0.7 smd paste+0 mask+0: 1(-2.15,1.27) 2(-2.15,0) 3(-2.15,-1.27) 5(2.15,-1.27) 6(2.15,0) 7(2.15,1.27)
  rect 0.7x1.5 smd paste+0 mask+0: 4(0,-2.15)
  rect 0.7x2.5 smd paste+0 mask+0: 8(0,1.75)
  silkscreen extent -3.67,-2.58 2.58,2.58, body extent -2.5,-2.5 2.5,2.5, height 1.55
FP-MSE-12-05-08-1666-IPC_B [mm]
  rect 1.54x0.455 smd paste+0 mask+0: 1(-2.11,1.625)
  rrect100% 1.54x0.455 smd paste+0 mask+0: 2(-2.11,0.975) 3(-2.11,0.325) 4(-2.11,-0.325) 5(-2.11,-0.975) 6(-2.11,-1.625) 7(2.11,-1.625) 8(2.11,-0.975) 9(2.11,-0.325) 10(2.11,0.325) 11(2.11,0.975) 12(2.11,1.625)
  rect 1.753x2.947 smd paste-1000 mask+0: 13(0,0)
  silkscreen extent -3.51,-2.7 2.02,2.7, body extent -3.13,-2.27 3.13,2.27, height 0.25
FP-RJ-8-IPC_B [mm]
  rect 1.505x0.455 smd paste+0 mask+0: 1(-1.1,0.975)
  rrect100% 1.505x0.455 smd paste+0 mask+0: 2(-1.1,0.325) 3(-1.1,-0.325) 4(-1.1,-0.975) 5(1.1,-0.975) 6(1.1,-0.325) 7(1.1,0.325) 8(1.1,0.975)
  silkscreen extent -2.55,-1.7 1.4,1.7, body extent -1.4,-1.45 1.4,1.45, height 1.45
FP-S2B-ZR_LF_SN-MFG [mm]
  rect 1.2x1.2 hole 0.7 paste-2539.97 mask+0: 1(-0.75,1.6)
  round 1.2 hole 0.7 paste-2539.97 mask+0: 2(0.75,1.6)
  silkscreen extent -2.25,-3 2.25,3.52, body extent -2.35,-3.1 2.35,3.1, height 0.25
FP-SOD323-MFG [mm]
  rect 0.59x0.45 smd paste+0 mask+0: 1(-1.055,0) 2(1.055,0)
  silkscreen extent -2.02,-0.7 0.9,0.7, body extent -1.45,-0.8 1.45,0.8, height 0.25
FP-XAL40-MFG [mm]
  rect 0.98x3.4 smd: 1(-1.185,0) 2(1.185,0)
  silkscreen extent -2.15,-2.15 2.15,2.15, body extent -2.25,-2.25 2.25,2.25, height 0.25
FP-XFL4020-MFG [mm]
  rect 0.98x3.4 smd paste+0 mask+0: 1(-1.185,0) 2(1.185,0)
  silkscreen extent -2.77,-2.15 2.15,2.15, body extent -2.25,-2.25 2.25,2.25, height 0.25
LED-0805 [mm] "SMD LED, 805, Body 2.0 x 1.3 mm (LxW typ)"
  rect 1.15x1.4 smd: 1(-0.975,0) 2(0.975,0)
  silkscreen extent -1.85,-0.6 -1.85,0.6, body extent -1,-0.62 1,0.63, height 0.75
LIGO-LOGO-SM [mil] "Smaller Ligo Logo"
  silkscreen extent -154,4 -36,122
MKS2B046801M00 [mm] "MKS2 PMC5 8.5 x 7.2 x 14.0"
  round 1.2 hole 0.7: 1(0,0) 2(5,0)
  silkscreen extent -1.1,-4.25 6.1,4.25, body extent -1.1,-4.25 6.1,4.25, height 14.1
MSD7342 [mil] "Common mode choke, MSD series"
  rect 43x103 smd: 1(67,10) 2(0,10) 3(0,-223) 4(67,-223)
  silkscreen extent -116,-256 184,70, body extent -114,-253 180,41, height 181
MSOP8 [mm] "MSOP Plastic Small-Outline Package"
  rect 0.42x1.6 smd: 1(-0.975,-2.205) 2(-0.325,-2.205) 3(0.325,-2.205) 4(0.975,-2.205) 5(0.975,2.195) 6(0.325,2.195) 7(-0.325,2.195) 8(-0.975,2.195)
  silkscreen extent -1.3,-0.77 1.3,0.76, body extent -1.5,-2.45 1.5,2.45, height 1.15
NETTIE1_SMDTOP [mil] "Tie two nets together"
  rect 10x10 smd mask-10: 1(0,0) 2(20,0)
  Top Layer region: -10,-10 30,-10 30,10 -10,10
ONSC-SOT-23-3-318-08_V [mm] "SOT23, 3-Leads, Body 2.92x1.3mm, Pitch 0.95mm"
  rect 0.9x0.8 smd: 1(-1,0.95) 2(-1,-0.95) 3(1,0)
  silkscreen extent -1.12,-1.46 0.65,2.03, body extent -0.65,-1.46 0.65,1.46, height 1.11
P50E-080-SR1 [mil] "3M Pak 50 Boardmount Plug"
  rect 50x50 hole 35: 1(-25,100)
  round 50 hole 35: 2(-25,-50) 3(-75,25) 4(-75,-125) 5(-125,100) 6(-125,-50) 7(-175,25) 8(-175,-125) 9(-225,100) 10(-225,-50) 11(-275,25) 12(-275,-125) 13(-325,100) 14(-325,-50) 15(-375,25) 16(-375,-125) 17(-425,100) 18(-425,-50) 19(-475,25) 20(-475,-125) 21(-525,100) 22(-525,-50) 23(-575,25) 24(-575,-125) 25(-625,100) 26(-625,-50) 27(-675,25) 28(-675,-125) 29(-725,100) 30(-725,-50) 31(-775,25) 32(-775,-125) 33(-825,100) 34(-825,-50) 35(-875,25) 36(-875,-125) 37(-925,100) 38(-925,-50) 39(-975,25) 40(-975,-125) 41(-1025,100) 42(-1025,-50) 43(-1075,25) 44(-1075,-125) 45(-1125,100) 46(-1125,-50) 47(-1175,25) 48(-1175,-125) 49(-1225,100) 50(-1225,-50) 51(-1275,25) 52(-1275,-125) 53(-1325,100) 54(-1325,-50) 55(-1375,25) 56(-1375,-125) 57(-1425,100) 58(-1425,-50) 59(-1475,25) 60(-1475,-125) 61(-1525,100) 62(-1525,-50) 63(-1575,25) 64(-1575,-125) 65(-1625,100) 66(-1625,-50) 67(-1675,25) 68(-1675,-125) 69(-1725,100) 70(-1725,-50) 71(-1775,25) 72(-1775,-125) 73(-1825,100) 74(-1825,-50) 75(-1875,25) 76(-1875,-125) 77(-1925,100) 78(-1925,-50) 79(-1975,25) 80(-1975,-125)
  round 110 hole 93: 81(200,-50) 82(-2200,-50)
  silkscreen extent -2325,-552 325,150, body extent -2298,-546 298,139, height 280
PCIeX4-GF-2D-1000-1K-O64 [mm] "Golden finger, PCIeX4, Dual, Opposite, Pitch 1mm, 64-Position"
  rect 0.7x3.2 smd far side paste-1: A1(-9.5,0.5)
  rect 0.7x4.2 smd far side paste-1: A2(-8.5,0) A3(-7.5,0) A4(-6.5,0) A5(-5.5,0) A6(-4.5,0) A7(-3.5,0) A8(-2.5,0) A9(-1.5,0) A10(-0.5,0) A11(0.5,0) A12(3.5,0) A13(4.5,0) A14(5.5,0) A15(6.5,0) A16(7.5,0) A17(8.5,0) A18(9.5,0) A19(10.5,0) A20(11.5,0) A21(12.5,0) A22(13.5,0) A23(14.5,0) A24(15.5,0) A25(16.5,0) A26(17.5,0) A27(18.5,0) A28(19.5,0) A29(20.5,0) A30(21.5,0) A31(22.5,0) A32(23.5,0)
  rect 0.7x4.2 smd paste-1: B1(-9.5,0) B2(-8.5,0) B3(-7.5,0) B4(-6.5,0) B5(-5.5,0) B6(-4.5,0) B7(-3.5,0) B8(-2.5,0) B9(-1.5,0) B10(-0.5,0) B11(0.5,0) B12(3.5,0) B13(4.5,0) B14(5.5,0) B15(6.5,0) B16(7.5,0) B18(9.5,0) B19(10.5,0) B20(11.5,0) B21(12.5,0) B22(13.5,0) B23(14.5,0) B24(15.5,0) B25(16.5,0) B26(17.5,0) B27(18.5,0) B28(19.5,0) B29(20.5,0) B30(21.5,0) B32(23.5,0)
  rect 0.7x3.2 smd paste-1: B17(8.5,0.5) B31(22.5,0.5)
SO-8_N [mm] "SOIC, 8-Leads, Body 4.9x3.9mm, Pitch 1.27mm, IPC Medium Density"
  oval 2.2x0.6 smd: 1(-2.4,1.905) 2(-2.4,0.635) 3(-2.4,-0.635) 4(-2.4,-1.905) 5(2.4,-1.905) 6(2.4,-0.635) 7(2.4,0.635) 8(2.4,1.905)
  silkscreen extent -2.52,-2.5 0.9,2.88, body extent -1.95,-2.45 1.95,2.45, height 1.75
SO-G3/C2.25 [mm] "SOT-23; 3 Leads; Body 3.0 x 2.5 mm, inc. leads (LxW max)"
  rect 0.95x1 smd: 1(-0.95,-1.125) 2(0.95,-1.125) 3(0,1.125)
  silkscreen extent -2.1,-1.25 1.32,1.13, body extent -1.45,-1.4 1.45,1.4, height 1.3
SO-G5/E2.4 [mm] "Small Outline; 5 Leads; Body 3.6 x 3.6 mm, inc. leads (LxW max)"
  rect 0.55x1.45 smd: 1(-0.95,-1.35) 2(0,-1.35) 3(0.95,-1.35) 4(0.95,1.35) 5(-0.95,1.35)
  silkscreen extent -1.67,-2.53 1.55,1.2, body extent -1.45,-1.4 1.45,1.4, height 1.45
SO-G6/E2.4 [mm] "Small Outline; 6 Leads; Body 3.6 x 3.6 mm, inc. leads (LxW max)"
  rect 0.55x1.45 smd: 1(-0.95,-1.35) 2(0,-1.35) 3(0.95,-1.35) 4(0.95,1.35) 5(0,1.35) 6(-0.95,1.35)
  silkscreen extent -1.67,-2.52 1.55,1.2, body extent -1.45,-1.4 1.45,1.4, height 1.45
SO-G8 [mm] "Small Outline; 8 Leads; Body Width 3.9 mm; Pitch 1.27 mm"
  rect 0.6x2.2 smd: 1(-1.905,-2.6) 2(-0.635,-2.6) 3(0.635,-2.6) 4(1.905,-2.6) 5(1.905,2.6) 6(0.635,2.6) 7(-0.635,2.6) 8(-1.905,2.6)
  silkscreen extent -2.88,-2.72 2.5,1.1, body extent -2.47,-3.06 2.48,3.06, height 1.75
TP1-BLK [mm] "Testpoint pin, black"
  round 2.54 hole 1.58: 1(0,0)
  body extent -1.27,-1.27 1.27,1.27, height 4.89
TP1-RED [mm] "Testpoint pin, red"
  round 2.54 hole 1.58: 1(0,0)
  body extent -1.27,-1.27 1.27,1.27, height 4.89
TP1-WHT [mm] "Testpoint pin, white"
  round 2.54 hole 1.58: 1(0,0)
  body extent -1.27,-1.27 1.27,1.27, height 4.89
TP1-YLW#1 [mm] "Testpoint pin, yellow"
  round 2.54 hole 1.58: 1(0,0)
  body extent -1.27,-1.27 1.27,1.27, height 4.89
TP1-YLW#2 [mm] "Testpoint pin, yellow"
  round 2.54 hole 1.58: 1(0,-0.05)
  body extent -1.27,-1.27 1.27,1.27, height 4.89
TP2 [mil] "Testpoint SMD minature"
  rect 70x135 smd: 1(0,0)
  body extent -20,-52 20,53, height 60
TSSO3x5-G10 [mm] "Shrink Small Outline; 10 Leads; Body Width 3 mm; Pitch 0.5 mm"
  rect 0.3x1.6 smd: 1(-1,-2.05) 2(-0.5,-2.05) 3(0,-2.05) 4(0.5,-2.05) 5(1,-2.05) 6(1,2.05) 7(0.5,2.05) 8(0,2.05) 9(-0.5,2.05) 10(-1,2.05)
  silkscreen extent -1.82,-2.18 1.58,0.85, body extent -1.5,-2.54 1.5,2.49, height 1.05
TSSOP14 [mm] "Shrink Small Outline; 14 Leads; Body Width 4.4 mm; Pitch 0.65 mm"
  rect 0.3x1.65 smd: 1(-1.95,-2.775) 2(-1.3,-2.775) 3(-0.65,-2.775) 4(0,-2.775) 5(0.65,-2.775) 6(1.3,-2.775) 7(1.95,-2.775) 8(1.95,2.775) 9(1.3,2.775) 10(0.65,2.775) 11(0,2.775) 12(-0.65,2.775) 13(-1.3,2.775) 14(-1.95,2.775)
  silkscreen extent -2.77,-2.9 2.55,1.55
TSSOP16 [mm] "Shrink Small Outline; 16 Leads; Body Width 4.4 mm; Pitch 0.65 mm"
  rect 0.3x1.65 smd: 1(-2.275,-2.775) 2(-1.625,-2.775) 3(-0.975,-2.775) 4(-0.325,-2.775) 5(0.325,-2.775) 6(0.975,-2.775) 7(1.625,-2.775) 8(2.275,-2.775) 9(2.275,2.775) 10(1.625,2.775) 11(0.975,2.775) 12(0.325,2.775) 13(-0.325,2.775) 14(-0.975,2.775) 15(-1.625,2.775) 16(-2.275,2.775)
  silkscreen extent -3.1,-2.9 2.55,1.55, body extent -2.5,-3.2 2.5,3.2, height 1.13
VISH-POWERPAKSO-8_A_V [mm] "SMD, 8-Leads, Body 6.15x5.155mm, Pitch 1.27mm"
  rect 1.27x0.61 smd: 1(-2.67,1.905) 2(-2.67,0.635) 3(-2.67,-0.635) 4(-2.67,-1.905)
  rect 1.02x0.61 smd: 5(2.795,-1.905) 6(2.795,-0.635) 7(2.795,0.635) 8(2.795,1.905)
  Top Layer region: -1.215,0.305 2.595,0.305 2.595,1.955 -1.215,1.955
  Top Layer region: -1.215,-1.955 2.595,-1.955 2.595,-0.305 -1.215,-0.305
  silkscreen extent -3.98,1.78 -3.73,2.03, body extent -3.08,-2.58 3.08,2.58, height 1.12
WM4200 [mil] "Locking 2 pin Molex"
  rect 62x62 hole 40: 1(0,0)
  round 62 hole 40: 2(100,0)
  silkscreen extent -50,-125 150,125, body extent -47,-122 147,128, height 420

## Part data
C1 C500: library part ChipCap, "C2220 22uF", Part Number=16MU226MD35750, Supplier Part Number 1=1189-2516-1-ND
C2 C4 C6 C187 C215 C248 C351A C351B C351C C351D C351E C351F C351G C351H C351I C351J C351K C351L C351M C351N C351O C351P C431A C431B C431C C431D C431E C431F C431G C431H C431I C431J C431K C431L C431M C431N C431O C431P: library part ChipCap
C3 C5 C7A C7B C7C C7D C8A C8B C8C C8D C43A C43B C43C C43D C44A C44B C44C C44D C122 C123 C124 C125 C126 C127 C128 C141 C142 C143 C150 C151 C165 C166 C167 C168 C169 C170 C171 C291A C291B C291C C291D C303A C303B C303C C303D C481 C482 C483 C484: library part ChipCap, "C1210 10uF", Part Number=CL32B106KBJNNNE, Supplier Part Number 1=1276-3387-1-ND
C9 C10 C11 C12 C13 C14 C15A C15B C15C C15D C19A C19B C19C C19D C20A C20B C20C C20D C27A C27B C27C C27D C31A C31B C31C C31D C35A C35B C35C C35D C36A C36B C36C C36D C51A C51B C51C C51D C52A C52B C52C C52D C287A C287B C287C C287D C295A C295B C295C C295D C299A C299B C299C C299D C307A C307B C307C C307D: library part ChipCap, "C0201 0.1uF", Part Number=490-GRM033Z71C104KE14DCT-ND
C59 C60 C62 C63 C64 C66 C68 C86 C87 C88 C94 C95 C101 C102 C114 C115 C138 C140 C146 C177 C180 C196 C197 C203 C212 C217 C230 C245 C249 C257 C266 C268 C281 C286 C335A C335B C335C C335D C335E C335F C335G C335H C335I C335J C335K C335L C335M C335N C335O C335P C367A C367B C367C C367D C367E C367F C367G C367H C367I C367J C367K C367L C367M C367N C367O C367P C415A C415B C415C C415D C415E C415F C415G C415H C415I C415J C415K C415L C415M C415N C415O C415P C447A C447B C447C C447D C447E C447F C447G C447H C447I C447J C447K C447L C447M C447N C447O C447P: library part ChipCap, "C0402 0.1uF", Part Number=CL05B104KA5NNNC, Supplier Part Number 1=1276-6720-1-ND
C61: library part "CapPolypropylene ECQPZ", "Polypropylene Film Capacitor, radial lead", Part Number=399-13063-ND
C65 C152 C155 C178 C179: library part ChipCap, "C0603 0.1uF", Part Number=CL10B104KB8NNNC, Supplier Part Number 1=1276-1000-1-ND
C67 C70 C71 C272: library part ChipCap, "C0402 1.0nF COG", Part Number=0402N102J250CT, Supplier Part Number 1=1292-1246-1-ND
C69 C283 C284 C285: library part ChipCap, "C0402 0.01uF", Part Number=CC0402JRX7R9BB103, Supplier Part Number 1=311-3339-1-ND
C72 C73 C84 C85 C112 C113 C148 C149 C185 C186 C204: library part ChipCap, "C1206 47uF", Part Number=C3216X5R1E476M160DC, Supplier Part Number 1=445-C3216X5R1E476M160DCCT-ND
C74 C75 C76 C77 C78 C79 C80 C81 C82 C83 C91 C92 C182 C183 C189 C191 C192 C199 C200 C201: library part ChipCap, "C0603 4.7uF", Part Number=CL10B475KQ8NQNC, Supplier Part Number 1=1276-2087-1-ND
C89 C97 C105 C153 C154 C190 C195 C198 C202 C479 C480: library part ChipCap, "C0603 1.0uF", Part Number=CL10B105KA8NNNC, Supplier Part Number 1=1276-1184-1-ND
C90 C103 C104 C116 C117 C147 C163 C164 C172 C173 C174 C175 C188 C193 C194 C232 C267: library part ChipCap, "C0805 10uF", Part Number=CL21A106KAYNNNG, Supplier Part Number 1=1276-6454-1-ND
C93 C100 C108 C109 C137 C139 C176 C181: library part ChipCap, "C0402 1.0uF", Part Number=C0402C105K4PACTU, Supplier Part Number 1=490-10017-1-ND
C96 C129 C130 C131 C132 C184: library part ChipCap, "C0402 0.1nF", Part Number=04025A101JAT2A, Supplier Part Number 1=478-1082-1-ND
C98 C99: library part CapFilmRadial, "Film Capacitor 6.8u Radial", Supplier Part Number 1=MKS2B046801M00KSSD
C106 C107: library part ChipCap, "C0402 1.8nF", Part Number=C0402C182J3GACTU, Supplier Part Number 1=399-17370-1-ND
C110: library part ChipCap, "C0402 5.6nF", Part Number=CL05B562KA5NNNC, Supplier Part Number 1=1276-1578-1-ND
C111: library part ChipCap, "C0402 2.7nF", Part Number=C0402C272K3RAC7867, Supplier Part Number 1=399-14439-1-ND
C118 C119 C120 C121: library part ChipCap, "C0402 47nF", Part Number=0402B473J250CT, Supplier Part Number 1=1292-1213-1-ND
C133 C134 C135 C136: library part ChipCap, "C1206 2.2u", Part Number=C1206C225J5RECAUTO, Supplier Part Number 1=399-C1206C225J5RECAUTOCT-ND
C144 C145: library part ChipCap, "C2220 47uF", Part Number=C5750X7R1E476M230KB, Supplier Part Number 1=445-C5750X7R1E476M230KBCT-ND
C156 C157 C158 C159 C160 C161 C162: library part ChipCap, "C1210 3.3uF Film", Part Number=16MU335MB33225, Supplier Part Number 1=1189-2517-1-ND
C205 C206 C207 C208 C209 C210 C211 C213 C214 C216 C218 C219 C220 C221 C222 C223 C224 C225 C226 C227 C228 C229 C231 C234 C235 C236 C237 C238 C239 C240 C241 C242 C243 C244 C246 C247 C250 C251 C252 C253 C254 C255 C256 C258 C259 C260 C261 C262 C263 C264 C265 C269 C270 C271 C273: library part CMP-2010-00306-2, "Cap Ceramic 470nF 4V X5R ±20% Pad SMD 0201 +85°C T/R", Part Number=LMK063BBJ474MPLF, Supplier Part Number 1=587-6388-1-ND
C233: library part CMP-2010-00306-2
C274 C275 C276 C277 C278 C279 C280 C282: library part ChipCap, "C0402 0.22uF", Part Number=TMK105B7224KV-FR, Supplier Part Number 1=587-6021-1-ND
C311A C311B C311C C311D C315A C315B C315C C315D: library part ChipCap, "C0402 0.2n", Part Number=0402N201J500CT, Supplier Part Number 1=1292-1279-1-ND
C319A C319B C319C C319D C319E C319F C319G C319H C319I C319J C319K C319L C319M C319N C319O C319P C383A C383B C383C C383D C383E C383F C383G C383H C383I C383J C383K C383L C383M C383N C383O C383P C399A C399B C399C C399D C399E C399F C399G C399H C399I C399J C399K C399L C399M C399N C399O C399P C463A C463B C463C C463D C463E C463F C463G C463H C463I C463J C463K C463L C463M C463N C463O C463P: library part ChipCap, "C0603 2.2n", Part Number=GCM1885C1H222FA16D, Supplier Part Number 1=490-16421-1-ND
D1 D2: library part CMP-12791-000031-1, "DIODE GEN PURP 85V 215MA SOD323", Supplier Part Number 1=BAV116WSQ-7DICT-ND
D3: library part DIODE_SHOTTKY, Part Number=LSM115JE3/TR13, Supplier Part Number 1=150-LSM115JE3/TR13CT-ND
D4 D5 D6 D7: library part DIODE_SHOTTKY, Part Number=DFLS230-7, Supplier Part Number 1=DFLS230DICT-ND
D8 D9: library part DIODE_SHOTTKY, "Single shottky diode", Part Number=CDBA340L-G, Supplier Part Number 1=641-1258-1-ND
DS1: library part LED, "Panel mount LED", Part Number=L71517CT-ND
DS2 DS3 DS4 DS5 DS6: "Panel mount LED", Part Number=L71517CT-ND
FL1 FL2: library part CMP-2000-05960-2, "FILTER LC TH", Supplier Part Number 1=490-5055-ND
FR1 FR2 FR3 FR4 FR5 FR6 FR7 FR8 FR9: library part BLM31PG121SN1, "ferrite bead, 120Ohm at 100MHz, 1206", Part Number=BLM31PG121SN1L, Supplier Part Number 1=490-1056-1-ND
J1: library part CMP-2000-07021-2, "CONN HEADER R/A 2POS 1.5MM", Part Number=S2B-ZR, Supplier Part Number 1=455-1669-ND
J2: "Connector", Part Number=WM10869-ND
L1 L2: library part CMP-2000-05090-4, "INDUCTOR, 2.2UH, 8A, 20%, 38MHZ, REEL", Supplier Part Number 1=2457-XFL4020-222MEC-ND
L3: library part CMP-11268-000187-1, "Fixed Inductors 3.3Uh Shld 5.2A 38.3mOhms AECQ2", Supplier Part Number 1=2457-XGL4020-332MEC-ND
L4: library part CMP-11268-000008-1, "INDUCTOR, 4.7uH", Part Number=XFL4020-472MEC, Supplier Part Number 1=2457-XFL4020-472MEC-ND
L5 L6 L7: library part MSD7342, "Shielded Coupled Inductors, MSD7342 series 8.2uH", Part Number=MSD7342-822MLC, Supplier Part Number 1=994-MSD7342-822MLC
L8: library part MSD7342, "Shielded Coupled Inductors, MSD7342 series 4.7uH", Part Number=MSD7342-472MLC, Supplier Part Number 1=994-MSD7342-472MLC
L9: library part ChipInductor, "Inductor", Part Number=994-1008CS-330XGLC
L10: library part ChipInductor, "Inductor", Part Number=994-1008CS-101XJLC
LOGO1: library part LIGO_logo, "NL"
MP4A MP4B MP4C MP4D: library part CMP-33535-000022-1, "HEATSINK FOR TO-268", Part Number=DA-T268-301E, Supplier Part Number 1=DA-T268-301ECT-ND
MP5 MP6 MP7 MP8: library part CMP-33535-000006-1, "HEATSINK FOR TO-263", Part Number=DA-T263-201E, Supplier Part Number 1=DA-T263-201ECT-ND
P1: library part "PE50E-080 Connector", "3M Pak 50 plug connector", Part Number=P50E-080P1-SR1-EA, Supplier Part Number 1=3M157515-ND
P2: library part CMP-0001-00031-2, "NL"
P3: library part Xilinx_JTAG_Header, "Xilinx JTAG header, 7-Pin, Dual row", Part Number=WM18863-ND
P4: library part WM4200, "Header, 2-Pin", Supplier Part Number 1=900-0022232021-ND
Q1 Q6 Q7 Q8 Q9 Q10: "FDV301N, Digital FET, N-channel, SOT23", Part Number=FDV301NCT-ND
Q2: library part CMP-2000-07602-1, "Dual N-Channel (D-S) MOSFET, 100 V, 36.7 A, -55 to 150 degC, 8-Pin SMD, RoHS, Tape and Reel", Part Number=AON6816, Supplier Part Number 1=785-1499-1-ND
Q3 Q4 Q5: library part CMP-1048-00670-1, "General Purpose Transistor, PNP Silicon, 3-Pin SOT-23, Pb-Free, Tape and Reel", Supplier Part Number 1=MMBT3906LT1GOSCT-ND
R1 R2 R72 R75 R83 R84 R86 R89 R287 R299 R300 R301 R302 R319A R319B R319C R319D: library part ChipRes1, "R0402 100", Part Number=RR0510P-101-D, Supplier Part Number 1=RR05P100DCT-ND
R3 R102 R108 R110 R111 R113 R116 R117 R148 R154 R157 R203 R238 R261 R265: library part ChipRes1, "R0402 10k", Part Number=ERA-2AEB103X, Supplier Part Number 1=P10KDCCT-ND
R4: library part ChipRes1, "R0402 1.33k", Part Number=ERA-2AEB1331X, Supplier Part Number 1=P1.33KDCCT-ND
R5 R155: library part ChipRes1, "R0402 13.3k", Part Number=ERA-2AEB1332X, Supplier Part Number 1=P13.3KDCCT-ND
R6 R71 R103 R109 R143 R205 R206 R209 R210 R247 R281 R286 R289 R291 R296 R303 R500: library part ChipRes1, "R0402 1.0k", Part Number=ERA-2AEB102X, Supplier Part Number 1=P1.0KDCCT-ND
R7A R7B R7C R7D R7E R7F R7G R7H R7I R7J R7K R7L R7M R7N R7O R7P R8A R8B R8C R8D R8E R8F R8G R8H R8I R8J R8K R8L R8M R8N R8O R8P R69 R70 R73 R74 R76 R77 R78 R79 R80 R81 R87 R91 R92 R93 R94 R95 R97 R101 R104 R188 R250 R256 R260 R267 R306 R309 R314 R315 R316 R318 R327A R327B R327C R327D: library part ChipRes1
R39A R39B R39C R39D R40A R40B R40C R40D: library part ChipRes1, "R0201 47k", Part Number=RMCF0201FT47K0CT-ND
R41A R41B R41C R41D R42A R42B R42C R42D: library part ChipRes1, "R0201 2k", Part Number=ERA-1AEB202C, Supplier Part Number 1=P2.0KBXCT-ND
R55A R55B R55C R55D R63A R63B R63C R63D: library part ChipRes1, "R0201 100k", Part Number=ERJ-1GNF1003C, Supplier Part Number 1=P122655CT-ND
R56A R56B R56C R56D: library part ChipRes1, "NL"
R67 R68 R82 R88 R90: library part ChipRes1, "R0402 1.8k", Part Number=RR05P1.8KDCT-ND
R85 R96 R107 R219 R220 R232 R234 R278 R280 R285 R288 R290 R293 R294 R295 R297 R298 R304: library part ChipRes1, "R0402 4.7k", Part Number=ERA-2AED472X, Supplier Part Number 1=P4.7KDECT-ND
R98 R312: library part ChipRes1, "R0402 22k", Part Number=ERA-2AED223X, Supplier Part Number 1=P22KDECT-ND
R99 R105 R282 R283 R311 R313 R351A R351B R351C R351D R351E R351F R351G R351H R351I R351J R351K R351L R351M R351N R351O R351P R367A R367B R367C R367D R367E R367F R367G R367H R367I R367J R367K R367L R367M R367N R367O R367P R415A R415B R415C R415D R415E R415F R415G R415H R415I R415J R415K R415L R415M R415N R415O R415P R431A R431B R431C R431D R431E R431F R431G R431H R431I R431J R431K R431L R431M R431N R431O R431P: library part ChipRes1, "R0402 49.9", Part Number=ERA-2AEB49R9X, Supplier Part Number 1=P49.9DCCT-ND
R100 R307: library part ChipRes1, "R0402 2.32k", Part Number=ERA-2AEB2321X, Supplier Part Number 1=P2.32KDCCT-ND
R106 R305 R310: library part ChipRes1, "R0402 1.6k", Part Number=ERA-2AEB162X, Supplier Part Number 1=P1.6KDCCT-ND
R112 R115: library part ChipRes1, "R0402 20k", Part Number=RT0402BRD0720KL, Supplier Part Number 1=YAG1388CT-ND
R114 R135 R137 R230 R279: library part ChipRes1, "R0603 1k", Part Number=RR0816P-102-D, Supplier Part Number 1=RR08P1.0KDCT-ND
R118 R121 R151 R152 R163 R164 R201 R202 R233 R236 R323A R323B R323C R323D R331A R331B R331C R331D: library part ChipRes1, "R0402 100k", Part Number=ERA-2AEB104X, Supplier Part Number 1=P100KDCCT-ND
R119 R120: library part ChipRes1, "R0402 2.0k", Part Number=ERA-2AEB202X, Supplier Part Number 1=P2.0KDCCT-ND
R122 R126 R131 R132 R133 R139 R161 R196 R235 R253 R254 R255 R257 R258 R259: library part ChipRes1, "R0603 220", Part Number=ERA-3AEB221V, Supplier Part Number 1=P220DBCT-ND
R123 R127 R169 R195: library part ChipRes1, "R0603 10k", Part Number=ERA-3AEB103V, Supplier Part Number 1=P10KDBCT-ND
R124 R125 R176 R185: library part ChipRes1, "R0603 100", Part Number=ERA-3AEB101V, Supplier Part Number 1=P100DBCT-ND
R128 R129 R165 R166 R167 R168 R173 R189 R190 R191 R192 R193 R194 R224 R227 R228 R248 R249 R272 R273 R276 R277: library part ChipRes1, "R0603 10m", Part Number=CFN0603AFZ-R010ELF, Supplier Part Number 1=118-CFN0603AFZ-R010ELFCT-ND
R130: library part ChipRes1, "R0603 1.37k", Part Number=ERA-3AEB1371V, Supplier Part Number 1=P1.37KDBCT-ND
R134 R138 R229: library part ChipRes1, "R0603 59k", Part Number=ERA-3AEB5902V, Supplier Part Number 1=P59KDBCT-ND
R136: library part ChipRes1, "R0603 3.7k", Part Number=RN73H1JTTD3701B25, Supplier Part Number 1=660-RN73H1JTD3701B25
R140: library part ChipRes1, "R0603 59k", Part Number=ERA-2AEB5902X, Supplier Part Number 1=P59KDCCT-ND
R141 R142 R175 R184: library part ChipRes1, "R0603 3.44k", Part Number=TNPW06033K44BEEN, Supplier Part Number 1=71-TNPW06033K44BEEN
R144 R292: library part ChipRes1, "R0402 4.99k", Part Number=RR0510P-4991-D, Supplier Part Number 1=RR05P4.99KDCT-ND
R145: library part ChipRes1, "R0402 15k", Part Number=ERA-2AEB153X, Supplier Part Number 1=P15KDCCT-ND
R146: library part ChipRes1, "R0402 9.31k", Part Number=311-2336-1-ND
R147: library part ChipRes1, "R0402 21.5k", Part Number=RR0510P-2152-D, Supplier Part Number 1=408-RR0510P-2152-DCT-ND
R149 R170 R171 R172: library part ChipRes1, "R0402 49.9k", Part Number=RR0510P-4992-D, Supplier Part Number 1=RR05P49.9KDCT-ND
R150 R162: library part ChipRes1, "R0402 130k", Part Number=RP73PF1E130KBTD, Supplier Part Number 1=A127522CT-ND
R153: library part ChipRes1, "R0402 31.6k", Part Number=RT0402DRE0731K6L, Supplier Part Number 1=311-2272-1-ND
R156: library part ChipRes1, "R0402 37.4k", Part Number=CR0402-FX-3742GLF, Supplier Part Number 1=YAG4250CT-ND
R158 R268 R271: library part ChipRes1, "R0402 7.15k", Part Number=RT0402BRD077K15L, Supplier Part Number 1=YAG1478CT-ND
R159: library part ChipRes1, "R0402 56.2k", Part Number=311-2303-1-ND
R160: library part ChipRes1, "R0603 6.49k", Part Number=ERA-3AEB6491V, Supplier Part Number 1=P6.49KDBCT-ND
R174: library part ChipRes1, "R0402 267k", Part Number=ERJ-2RKF2673X, Supplier Part Number 1=P267KLCT-ND
R177 R179 R181 R186: library part ChipRes1, "R0402 150", Part Number=ERA-2AEB151X, Supplier Part Number 1=667-ERA-2AEB151X
R178 R182 R183: library part ChipRes1, "R0402 300", Part Number=RR05P300DCT-ND
R180: library part ChipRes1, "R0402 249k", Part Number=RC0402FR-07249KL, Supplier Part Number 1=311-249KLRCT-ND
R187: library part ChipRes1, "R0402 47k", Part Number=RG10P47KBCT-ND
R197 R198 R200 R223: library part ChipRes1, "R0201 1k", Part Number=ERA-1AEB102C, Supplier Part Number 1=P1.0KBXCT-ND
R199 R222: library part RW1S0CK, "Four-Terminal Current Sense Resistor", Part Number=FC4L16R010FER, Supplier Part Number 1=FC4L16R010FERCT-ND
R204 R241 R242: library part ChipRes1, "R0402 34.8k", Part Number=RT0402DRD0734K8L, Supplier Part Number 1=311-2174-1-ND
R207: library part ChipRes1, "R0402 14k", Part Number=ERA-2AEB1402X, Supplier Part Number 1=P14KDCCT-ND
R208 R246 R252: library part ChipRes1, "R0402 0", Part Number=AC0402FR-070RL, Supplier Part Number 1=13-AC0402FR-070RLCT-ND
R211 R212 R214 R217: library part ChipRes1, "R0402 76.8k", Part Number=RT0402DRE0776K8L, Supplier Part Number 1=311-2319-1-ND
